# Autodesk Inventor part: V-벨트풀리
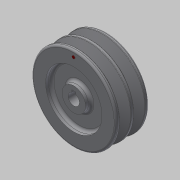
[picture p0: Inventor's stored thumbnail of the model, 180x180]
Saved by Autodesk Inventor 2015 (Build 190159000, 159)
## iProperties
Created: 2016-08
Part Number: V-벨트풀리
Material: 알루미늄 6061
Document SubType Name: Modeling
Designer: mduedu
Density: 2.71 g/cm^3
Appearance: 기본값
Mass: 380.117 g
Surface Area: 333.15 cm^2
Volume: 140.265 cm^3
Author: mduedu
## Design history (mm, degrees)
sketch "스케치1"
  geometry: L1 (0, 17.5)-(0, -17.5); L2 (0, -17.5)-(45, -17.5); L3 (45, -17.5)-(45, 17.5); L4 (45, 17.5)-(0, 17.5); L5 (45, -1.524)-(32.5, -5.346); L6 (32.5, -5.346)-(32.5, -9.654); L7 (32.5, -9.654)-(45, -13.476); L8 (45, 13.476)-(32.5, 9.654); L9 (32.5, 9.654)-(32.5, 5.346); L10 (32.5, 5.346)-(45, 1.524); L11 (40.5, 17.5)-(40.5, -17.5); L12 (45, -7.5)-(0, -7.5); L13 (45, 7.5)-(0, 7.5); 8 further points
  constraints: 26 end point, 20 point on line, 6 perpendicular, 3 equal length, 3 midpoint, 2 collinear, 1 coincident, 1 horizontal, 1 vertical
  dimensions: "d43" = 90 diameter of L3 L1; "d45" = 34 deg angle of L7 L5; "d47" = 34 deg angle of L8 L10; "d49" = 9.2 distance of point (40.5, -12.1) point (40.5, -2.9); "d50" = 9.2 distance of point (40.5, 12.1) point (40.5, 2.9) (derived); "d51" = 10 distance between parallel lines of L12 L2; "d52" = 10 distance between parallel lines of L13 L4; "d53" = 15 distance between parallel lines of L12 L13; "d54" = 4.5 distance between parallel lines of L11 L3; "d55" = 8 distance between parallel lines of L6 L11
revolve "회전1" sketch "스케치1" stored, may be unused: angle "d8" = 90 deg
sketch "스케치2"
  geometry: L1 (-2, 0)-(2, 0); L2 (2, 0)-(2, 7.8); L3 (2, 7.8)-(-2, 7.8); L4 (-2, 7.8)-(-2, 0); C1 r 6 at (0, 0); 3 further points
  constraints: 8 end point, 3 coincident, 2 parallel, 1 centre point, 1 horizontal, 1 midpoint, 1 perpendicular
  dimensions: "d9" = 12 diameter of C1; "d11" = 4 distance of L2.end L3.end; "d12" = 7.8 distance of L1.end L2.end
extrude "돌출1" cut sketch "스케치2" stored distance "d13" = 10; taper "d14" = 0 deg
sketch "스케치4"
  geometry: C1 r 30 at (0, 0); C2 r 12.5 at (0, 0); 2 further points
  constraints: 3 coincident, 2 centre point
  dimensions: "d30" = 60 diameter of C1; "d31" = 25 diameter of C2
extrude "돌출2" cut sketch "스케치4" distance "d32" = 6; taper "d33" = 0 deg
fillet "모깎기6" dims "d34" = 3
fillet "모깎기8" dims "d56" = 0.5, "d57" = 1, "d58" = 2
chamfer "모따기1" distance "d26" = 0.5; stored, may be unused: second distance "d27" = 2, angle "d28" = 45 deg
sketch "스케치5" dims "d38" = 78
  geometry: C1 r 1.5 at (0, 39); 3 further points
  constraints: 2 coincident, 2 vertical alignment, 1 centre point, 2 other
  dimensions: "d40" = 3 diameter of C1
extrude "돌출3" join sketch "스케치5" distance "d41" = 0.5; taper "d42" = 0 deg
node "솔리드1"
mirror "대칭2"
